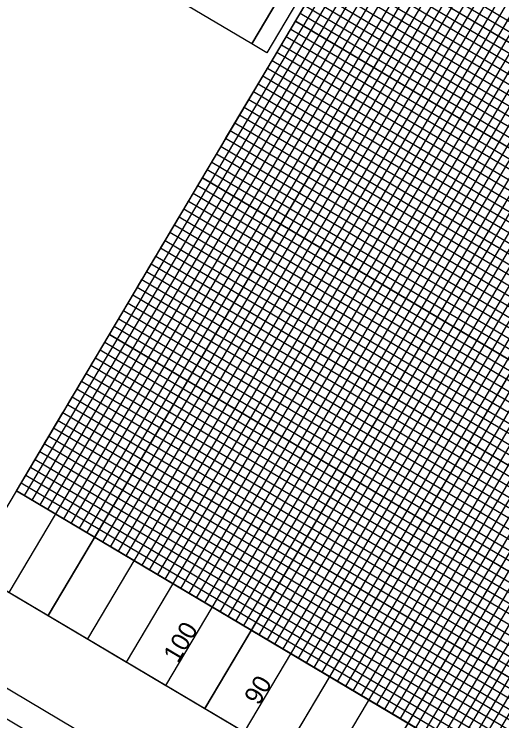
# Model space of a CAD drawing. Extents: x 2137081 to 2142019, y 404041 to 411238.
# Drawn here: x 2140819.3 to 2141087, y 409361 to 409749.2 of the extents above; entities that cross this region are included whole.
import ezdxf

# ---------------------------------------------------------------- set-up
doc = ezdxf.new("R2010")
doc.units = 0
for name, color, linetype in [('Exist Vertical Profile Vertical Axis Label', 7, 'Continuous'), ('Prop Dimension Text', 7, 'Continuous'), ('Sheet Block Revision CELL', 7, 'Continuous'), ('Sheet Clip Boundary CELL', 7, 'Continuous'), ('Sheet DOT Grid CELL', 7, 'Continuous'), ('Sheet Layout Profile Border Port 2', 7, 'Continuous'), ('Sheet Plan And Profile CELL', 7, 'Continuous'), ('Sheet Profile Grid Major CELL', 7, 'Continuous'), ('Sheet Profile Grid Middle CELL', 7, 'Continuous'), ('Sheet Profile Grid Minor CELL', 7, 'Continuous')]:
    doc.layers.add(name, color=color, linetype=linetype)

msp = doc.modelspace()

# ---------------------------------------------------------------- linework, layer by layer
at = {"layer": 'Prop Dimension Text'}
for points in [[(2141069.43, 409934.69), (2140949.64, 409732.86), (2140867.04, 409781.89), (2140986.83, 409983.72)], [(2140949.64, 409732.86), (2141069.43, 409934.69), (2141077.67, 409929.8), (2140957.88, 409727.97)]]:
    msp.add_lwpolyline(points, close=True, dxfattribs=at)
at = {"layer": 'Sheet Block Revision CELL'}
msp.add_line((2141016.6, 409259.3), (2140336.69, 409662.85), dxfattribs=at)
msp.add_lwpolyline([(2141009.18, 409246.79), (2140329.27, 409650.34), (2140360.17, 409702.41), (2141040.08, 409298.86)], close=True, dxfattribs=at)
at = {"layer": 'Sheet Clip Boundary CELL'}
msp.add_lwpolyline([(2140795, 409444.32), (2141473.2, 410586.96), (2141453.94, 410598.39), (2141513.05, 410697.97), (2141213, 410886.12), (2141134.78, 410754.33), (2141040.49, 410810.3), (2140938.2, 410637.97), (2140883.25, 410670.58), (2140322.04, 409725.04)], close=True, dxfattribs=at)
at = {"layer": 'Sheet DOT Grid CELL'}
for p, q in [((2140795, 409444.32), (2141560.61, 410734.22)), ((2140838, 409418.8), (2141603.6, 410708.7)), ((2140880.99, 409393.28), (2141646.6, 410683.18)), ((2140923.99, 409367.76), (2141689.6, 410657.66)), ((2140966.99, 409342.24), (2141732.59, 410632.14)), ((2141009.98, 409316.72), (2141775.59, 410606.62)), ((2140999.16, 409788.3), (2141407.63, 409545.85)), ((2140973.64, 409745.3), (2141382.11, 409502.86)), ((2140948.12, 409702.3), (2141356.59, 409459.86)), ((2140922.6, 409659.3), (2141331.07, 409416.86)), ((2140897.08, 409616.31), (2141305.55, 409373.87)), ((2140871.56, 409573.31), (2141280.03, 409330.87)), ((2140846.04, 409530.31), (2141254.51, 409287.87)), ((2140820.52, 409487.32), (2141228.99, 409244.88))]:
    msp.add_line(p, q, dxfattribs=at)
at = {"layer": 'Sheet Layout Profile Border Port 2'}
msp.add_lwpolyline([(2140820.52, 409487.32), (2141535.09, 410691.23), (2141943.55, 410448.78), (2141228.99, 409244.88)], close=True, dxfattribs=at)
at = {"layer": 'Sheet Plan And Profile CELL'}
msp.add_lwpolyline([(2141087.64, 411014.95), (2140322.04, 409725.04), (2141224.97, 409189.12), (2141990.57, 410479.02)], close=True, dxfattribs=at)
at = {"layer": 'Sheet Profile Grid Major CELL'}
for points in [[(2140795, 409444.32), (2141560.61, 410734.22)], [(2141603.6, 410708.7), (2140838, 409418.8), (2140880.99, 409393.28), (2141646.6, 410683.18)], [(2141689.6, 410657.66), (2140923.99, 409367.76), (2140966.99, 409342.24), (2141732.59, 410632.14)], [(2141775.59, 410606.62), (2141009.98, 409316.72), (2141052.98, 409291.2), (2141818.59, 410581.1)], [(2141382.11, 409502.86), (2140973.64, 409745.3), (2140999.16, 409788.3), (2141407.63, 409545.85)], [(2141331.07, 409416.86), (2140922.6, 409659.3), (2140948.12, 409702.3), (2141356.59, 409459.86)], [(2141280.03, 409330.87), (2140871.56, 409573.31), (2140897.08, 409616.31), (2141305.55, 409373.87)], [(2141228.99, 409244.88), (2140820.52, 409487.32), (2140846.04, 409530.31), (2141254.51, 409287.87)], [(2140795, 409444.32), (2141203.47, 409201.88)]]:
    msp.add_lwpolyline(points, dxfattribs=at)
at = {"layer": 'Sheet Profile Grid Middle CELL'}
for p, q in [((2140816.5, 409431.56), (2141582.1, 410721.46)), ((2141625.1, 410695.94), (2140859.49, 409406.04)), ((2140902.49, 409380.52), (2141668.1, 410670.42)), ((2141711.09, 410644.9), (2140945.49, 409355)), ((2140988.48, 409329.48), (2141754.09, 410619.38)), ((2141797.09, 410593.86), (2141031.48, 409303.96)), ((2140859.49, 409406.04), (2140902.49, 409380.52))]:
    msp.add_line(p, q, dxfattribs=at)
for points in [[(2141394.87, 409524.35), (2140986.4, 409766.8), (2141011.92, 409809.79), (2141420.39, 409567.35)], [(2141343.83, 409438.36), (2140935.36, 409680.8), (2140960.88, 409723.8), (2141369.35, 409481.36)], [(2141292.79, 409352.37), (2140884.32, 409594.81), (2140909.84, 409637.81), (2141318.31, 409395.36)], [(2141241.75, 409266.37), (2140833.28, 409508.82), (2140858.8, 409551.81), (2141267.27, 409309.37)]]:
    msp.add_lwpolyline(points, dxfattribs=at)
at = {"layer": 'Sheet Profile Grid Minor CELL'}
for points in [[(2141539.38, 410688.67), (2140824.82, 409484.77)], [(2141547.98, 410683.57), (2140833.42, 409479.66), (2140829.12, 409482.21), (2141543.68, 410686.12)], [(2141560.88, 410675.91), (2140846.32, 409472.01), (2140842.02, 409474.56), (2140837.72, 409477.11), (2141552.28, 410681.02)], [(2141569.48, 410670.81), (2140854.92, 409466.9), (2140850.62, 409469.45), (2141565.18, 410673.36)], [(2141582.38, 410663.15), (2140867.82, 409459.25), (2140863.52, 409461.8), (2140859.22, 409464.35), (2141573.78, 410668.26)], [(2141590.98, 410658.05), (2140876.42, 409454.14), (2140872.12, 409456.69), (2141586.68, 410660.6)], [(2141603.88, 410650.39), (2140889.31, 409446.49), (2140885.01, 409449.04), (2140880.72, 409451.59), (2141595.28, 410655.5)], [(2141612.48, 410645.29), (2140897.91, 409441.38), (2140893.61, 409443.93), (2141608.18, 410647.84)], [(2140910.81, 409433.73), (2140906.51, 409436.28), (2140902.21, 409438.83), (2141616.78, 410642.74)], [(2141629.68, 410635.08), (2140915.11, 409431.17), (2140910.81, 409433.73), (2141625.38, 410637.63)], [(2141638.28, 410629.98), (2140923.71, 409426.07), (2140919.41, 409428.62), (2141633.98, 410632.53)], [(2141651.18, 410622.32), (2140936.61, 409418.41), (2140932.31, 409420.97), (2141646.88, 410624.87)], [(2141659.78, 410617.22), (2140945.21, 409413.31), (2140940.91, 409415.86), (2141655.48, 410619.77)], [(2141672.67, 410609.56), (2140958.11, 409405.65), (2140953.81, 409408.21), (2141668.38, 410612.11)], [(2141681.27, 410604.46), (2140966.71, 409400.55), (2140962.41, 409403.1), (2141676.97, 410607.01)], [(2141694.17, 410596.8), (2140979.61, 409392.89), (2140975.31, 409395.45), (2141689.87, 410599.35)], [(2141702.77, 410591.7), (2140988.21, 409387.79), (2140983.91, 409390.34), (2141698.47, 410594.25)], [(2141715.67, 410584.04), (2141001.11, 409380.13), (2140996.81, 409382.69), (2141711.37, 410586.59)], [(2141724.27, 410578.94), (2141009.71, 409375.03), (2141005.41, 409377.58), (2141719.97, 410581.49)], [(2141737.17, 410571.28), (2141022.6, 409367.37), (2141018.3, 409369.92), (2141732.87, 410573.83)], [(2141745.77, 410566.18), (2141031.2, 409362.27), (2141026.9, 409364.82), (2141741.47, 410568.73)], [(2141758.67, 410558.52), (2141044.1, 409354.61), (2141039.8, 409357.16), (2141754.37, 410561.07)], [(2141767.27, 410553.42), (2141052.7, 409349.51), (2141048.4, 409352.06), (2141762.97, 410555.97)], [(2141780.17, 410545.76), (2141065.6, 409341.85), (2141061.3, 409344.4), (2141775.87, 410548.31)], [(2141788.77, 410540.66), (2141074.2, 409336.75), (2141069.9, 409339.3), (2141784.47, 410543.21)], [(2141410.18, 409550.15), (2141001.71, 409792.59), (2141004.27, 409796.89), (2141412.73, 409554.45)], [(2141402.53, 409537.25), (2140994.06, 409779.7), (2140996.61, 409784), (2141405.08, 409541.55)], [(2141397.42, 409528.65), (2140988.95, 409771.1), (2140991.51, 409775.4), (2141399.97, 409532.95)], [(2141389.77, 409515.76), (2140981.3, 409758.2), (2140983.85, 409762.5), (2141392.32, 409520.06)], [(2141384.66, 409507.16), (2140976.19, 409749.6), (2140978.74, 409753.9), (2141387.21, 409511.46)], [(2141377.01, 409494.26), (2140968.54, 409736.7), (2140971.09, 409741), (2141379.56, 409498.56)], [(2141371.9, 409485.66), (2140963.43, 409728.1), (2140965.98, 409732.4), (2141374.45, 409489.96)], [(2141364.25, 409472.76), (2140955.78, 409715.2), (2140958.33, 409719.5), (2141366.8, 409477.06)], [(2141359.14, 409464.16), (2140950.67, 409706.6), (2140953.22, 409710.9), (2141361.69, 409468.46)], [(2141351.49, 409451.26), (2140943.02, 409693.7), (2140945.57, 409698), (2141354.04, 409455.56)], [(2141346.38, 409442.66), (2140937.91, 409685.1), (2140940.46, 409689.4), (2141348.93, 409446.96)], [(2141338.73, 409429.76), (2140930.26, 409672.2), (2140932.81, 409676.5), (2141341.28, 409434.06)], [(2141333.62, 409421.16), (2140925.15, 409663.6), (2140927.7, 409667.9), (2141336.17, 409425.46)], [(2141325.97, 409408.26), (2140917.5, 409650.71), (2140920.05, 409655.01), (2141328.52, 409412.56)], [(2141320.86, 409399.66), (2140912.39, 409642.11), (2140914.94, 409646.41), (2141323.41, 409403.96)], [(2141313.21, 409386.77), (2140904.74, 409629.21), (2140907.29, 409633.51), (2141315.76, 409391.06)], [(2141308.1, 409378.17), (2140899.63, 409620.61), (2140902.18, 409624.91), (2141310.65, 409382.47)], [(2141300.45, 409365.27), (2140891.98, 409607.71), (2140894.53, 409612.01), (2141303, 409369.57)], [(2141295.34, 409356.67), (2140886.87, 409599.11), (2140889.42, 409603.41), (2141297.89, 409360.97)], [(2141287.69, 409343.77), (2140879.22, 409586.21), (2140881.77, 409590.51), (2141290.24, 409348.07)], [(2141282.58, 409335.17), (2140874.11, 409577.61), (2140876.66, 409581.91), (2141285.13, 409339.47)], [(2141274.93, 409322.27), (2140866.46, 409564.71), (2140869.01, 409569.01), (2141277.48, 409326.57)], [(2141269.82, 409313.67), (2140861.35, 409556.11), (2140863.9, 409560.41), (2141272.37, 409317.97)], [(2141262.17, 409300.77), (2140853.7, 409543.21), (2140856.25, 409547.51), (2141264.72, 409305.07)], [(2141257.06, 409292.17), (2140848.59, 409534.61), (2140851.14, 409538.91), (2141259.61, 409296.47)], [(2141249.4, 409279.27), (2140840.94, 409521.72), (2140843.49, 409526.01), (2141251.96, 409283.57)], [(2141244.3, 409270.67), (2140835.83, 409513.12), (2140838.38, 409517.42), (2141246.85, 409274.97)], [(2141236.64, 409257.78), (2140828.18, 409500.22), (2140830.73, 409504.52), (2141239.2, 409262.07)], [(2141231.54, 409249.18), (2140823.07, 409491.62), (2140825.62, 409495.92), (2141234.09, 409253.48)]]:
    msp.add_lwpolyline(points, dxfattribs=at)

# ---------------------------------------------------------------- texts
at = {"layer": 'Exist Vertical Profile Vertical Axis Label'}
for s, p in [('100', (2140909.15, 409392.23)), ('90', (2140953.55, 409369.08))]:
    msp.add_text(s, height=10, rotation=59.3093, dxfattribs=at).set_placement(p)

doc.saveas('drawing.dxf')
